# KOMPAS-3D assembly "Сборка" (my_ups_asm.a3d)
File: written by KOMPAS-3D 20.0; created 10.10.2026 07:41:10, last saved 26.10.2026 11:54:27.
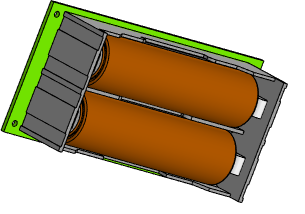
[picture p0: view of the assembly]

Document properties: Полное имя файла: D:\RicWork\Project-EPS32\box_compas\ups 18650\my_ups_asm.a3d

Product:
- Part/product: Сборка
    Масса: 0.425781
  - Component [detail]: Деталь  | Масса: 0.123603; source file: battery 18650 case x2.m3d
  - Component [detail]: Деталь  | Масса: 0.0459981; source file: my_ups.m3d
  - Component [detail]: Деталь  | qty 2  | Масса: 0.12809; source file: 18650 acc.m3d

Referenced files in D:\RicWork\Project-EPS32\box_compas\ups 18650\: my_ups.m3d, 18650 acc.m3d, battery 18650 case x2.m3d
Referenced files in D:\RicWork\Project-EPS32\box_compas\18650\: 18650 acc.m3d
